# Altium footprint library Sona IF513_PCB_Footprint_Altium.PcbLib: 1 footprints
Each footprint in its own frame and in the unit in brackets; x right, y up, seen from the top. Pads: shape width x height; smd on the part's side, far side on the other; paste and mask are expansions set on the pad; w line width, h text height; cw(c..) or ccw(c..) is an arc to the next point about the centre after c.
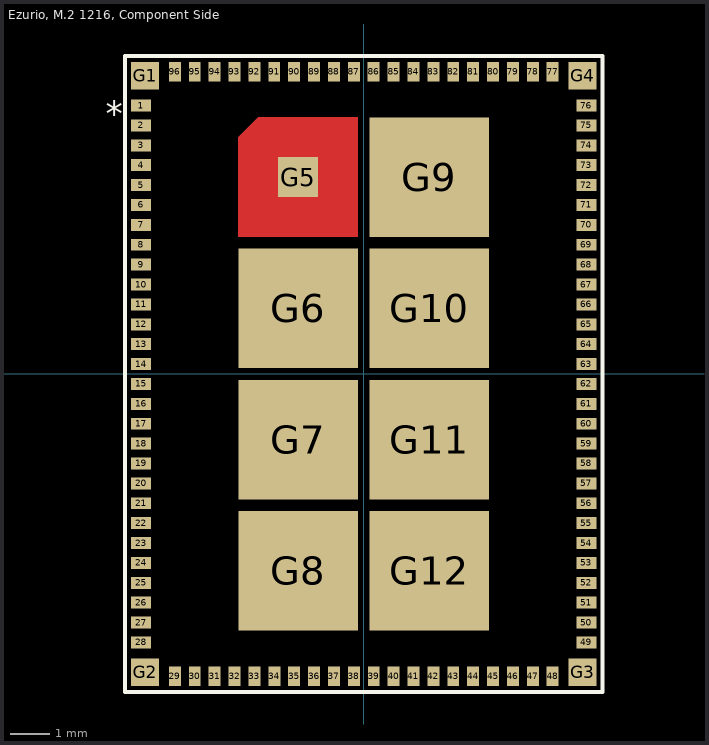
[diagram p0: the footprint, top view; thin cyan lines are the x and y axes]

## Ezurio, M.2 1216, Component Side [mm] "Ezurio, M2.1216, Component Side"
height 1.81
pads (108):
  rect 0.5x0.3 smd mask+0.051: 1(-5.6,6.75) 2(-5.6,6.25) 3(-5.6,5.75) 4(-5.6,5.25) 5(-5.6,4.75) 6(-5.6,4.25) 7(-5.6,3.75) 8(-5.6,3.25) 9(-5.6,2.75) 10(-5.6,2.25) 11(-5.6,1.75) 12(-5.6,1.25) 13(-5.6,0.75) 14(-5.6,0.25) 15(-5.6,-0.25) 16(-5.6,-0.75) 17(-5.6,-1.25) 18(-5.6,-1.75) 19(-5.6,-2.25) 20(-5.6,-2.75) 21(-5.6,-3.25) 22(-5.6,-3.75) 23(-5.6,-4.25) 24(-5.6,-4.75) 25(-5.6,-5.25) 26(-5.6,-5.75) 27(-5.6,-6.25) 28(-5.6,-6.75) 49(5.6,-6.75) 50(5.6,-6.25) 51(5.6,-5.75) 52(5.6,-5.25) 53(5.6,-4.75) 54(5.6,-4.25) 55(5.6,-3.75) 56(5.6,-3.25) 57(5.6,-2.75) 58(5.6,-2.25) 59(5.6,-1.75) 60(5.6,-1.25) 61(5.6,-0.75) 62(5.6,-0.25) 63(5.6,0.25) 64(5.6,0.75) 65(5.6,1.25) 66(5.6,1.75) 67(5.6,2.25) 68(5.6,2.75) 69(5.6,3.25) 70(5.6,3.75) 71(5.6,4.25) 72(5.6,4.75) 73(5.6,5.25) 74(5.6,5.75) 75(5.6,6.25) 76(5.6,6.75)
  rect 0.3x0.5 smd mask+0.051: 29(-4.749,-7.6) 30(-4.249,-7.6) 31(-3.75,-7.6) 32(-3.249,-7.6) 33(-2.75,-7.6) 34(-2.249,-7.6) 35(-1.749,-7.6) 36(-1.25,-7.6) 37(-0.749,-7.6) 38(-0.25,-7.6) 39(0.251,-7.6) 40(0.751,-7.6) 41(1.25,-7.6) 42(1.751,-7.6) 43(2.25,-7.6) 44(2.751,-7.6) 45(3.251,-7.6) 46(3.75,-7.6) 47(4.251,-7.6) 48(4.75,-7.6) 77(4.75,7.6) 78(4.25,7.6) 79(3.75,7.6) 80(3.25,7.6) 81(2.75,7.6) 82(2.25,7.6) 83(1.75,7.6) 84(1.25,7.6) 85(0.75,7.6) 86(0.25,7.6) 87(-0.25,7.6) 88(-0.75,7.6) 89(-1.25,7.6) 90(-1.75,7.6) 91(-2.25,7.6) 92(-2.75,7.6) 93(-3.25,7.6) 94(-3.75,7.6) 95(-4.25,7.6) 96(-4.75,7.6)
  rect 0.7x0.7 smd mask+0.051: G1(-5.5,7.5) G2(-5.5,-7.5) G3(5.5,-7.5) G4(5.5,7.5)
  rect 1x1 smd mask+0.051: G5(-1.65,4.95)
  rect 3x3 smd mask+0.051: G6(-1.65,1.65) G7(-1.65,-1.65) G8(-1.65,-4.95) G9(1.65,4.95) G10(1.65,1.65) G11(1.65,-1.65) G12(1.65,-4.95)
Top Layer:
  region: -2.65,6.45 -0.15,6.45 -0.15,3.45 -3.15,3.45 -3.15,5.95
Top Overlay:
  lines w0.102: -6,-8 6,-8 6,8 -6,8 -6,-8
  text "*" at -6.49,6.246 h0.64
Top Paste:
  region: -2.65,6.45 -0.15,6.45 -0.15,3.45 -3.15,3.45 -3.15,5.95
Top Solder:
  region: -2.669,6.5 -0.1,6.5 -0.1,3.4 -3.204,3.4 -3.204,5.965
Mechanical 13:
  lines w0.025: -6,4.2 -6,-8 ; 6,4.2 6,-8 ; -6,-8 -6,8 6,8 6,-8 ; -6,-8 6,-8 ; -6,-8 6,-8
  text "*" at -5.725,6.304 h0.64
  text ".Designator" at -6.66,8.617 h1.14
3D body: height 0.01, standoff 0, extent -3.15,3.45 -0.15,6.45
3D body: height 0.01, standoff 0, extent -5.85,-7.85 -5.15,-7.15
3D body: height 0.01, standoff 0, extent 0.15,3.45 3.15,6.45
3D body: height 0.01, standoff 0, extent 0.15,0.15 3.15,3.15
3D body: height 0.01, standoff 0, extent -3.15,0.15 -0.15,3.15
3D body: height 0.01, standoff 0, extent -3.15,-3.15 -0.15,-0.15
3D body: height 0.01, standoff 0, extent 0.15,-3.15 3.15,-0.15
3D body: height 0.01, standoff 0, extent 0.15,-6.45 3.15,-3.45
3D body: height 0.01, standoff 0, extent -3.15,-6.45 -0.15,-3.45
3D body: height 0.01, standoff 0, extent -5.85,-5.9 -5.35,-5.6
3D body: height 0.01, standoff 0, extent -5.85,-6.4 -5.35,-6.1
3D body: height 0.01, standoff 0, extent -5.85,-6.9 -5.35,-6.6
3D body: height 0.01, standoff 0, extent -5.85,-5.4 -5.35,-5.1
3D body: height 0.01, standoff 0, extent 5.15,-7.85 5.85,-7.15
3D body: height 0.01, standoff 0, extent 5.35,-6.9 5.85,-6.6
3D body: height 0.01, standoff 0, extent 5.35,-6.4 5.85,-6.1
3D body: height 0.01, standoff 0, extent 5.35,-5.9 5.85,-5.6
3D body: height 0.01, standoff 0, extent 5.35,-5.4 5.85,-5.1
3D body: height 0.01, standoff 0, extent 5.35,-4.9 5.85,-4.6
3D body: height 0.01, standoff 0, extent 5.35,-4.4 5.85,-4.1
3D body: height 0.01, standoff 0, extent 5.35,-3.9 5.85,-3.6
3D body: height 0.01, standoff 0, extent 5.35,-3.4 5.85,-3.1
3D body: height 0.01, standoff 0, extent 5.35,-2.9 5.85,-2.6
3D body: height 0.01, standoff 0, extent 5.35,-2.4 5.85,-2.1
3D body: height 0.01, standoff 0, extent 5.35,-1.9 5.85,-1.6
3D body: height 0.01, standoff 0, extent 5.35,-1.4 5.85,-1.1
3D body: height 0.01, standoff 0, extent 5.35,-0.9 5.85,-0.6
3D body: height 0.01, standoff 0, extent 5.35,-0.4 5.85,-0.1
3D body: height 0.01, standoff 0, extent 5.35,0.1 5.85,0.4
3D body: height 0.01, standoff 0, extent 5.35,0.6 5.85,0.9
3D body: height 0.01, standoff 0, extent 5.35,1.1 5.85,1.4
3D body: height 0.01, standoff 0, extent 5.35,1.6 5.85,1.9
3D body: height 0.01, standoff 0, extent 5.35,2.1 5.85,2.4
3D body: height 0.01, standoff 0, extent 5.35,2.6 5.85,2.9
3D body: height 0.01, standoff 0, extent 5.35,3.1 5.85,3.4
3D body: height 0.01, standoff 0, extent 5.35,3.6 5.85,3.9
3D body: height 0.01, standoff 0, extent 5.35,4.1 5.85,4.4
3D body: height 0.01, standoff 0, extent 5.35,4.6 5.85,4.9
3D body: height 0.01, standoff 0, extent 5.35,5.1 5.85,5.4
3D body: height 0.01, standoff 0, extent 5.35,5.6 5.85,5.9
3D body: height 0.01, standoff 0, extent 5.35,6.1 5.85,6.4
3D body: height 0.01, standoff 0, extent 5.35,6.6 5.85,6.9
3D body: height 0.01, standoff 0, extent 4.6,7.35 4.9,7.85
3D body: height 0.01, standoff 0, extent 4.1,7.35 4.4,7.85
3D body: height 0.01, standoff 0, extent 3.6,7.35 3.9,7.85
3D body: height 0.01, standoff 0, extent 3.1,7.35 3.4,7.85
3D body: height 0.01, standoff 0, extent 2.6,7.35 2.9,7.85
3D body: height 0.01, standoff 0, extent 2.1,7.35 2.4,7.85
3D body: height 0.01, standoff 0, extent 1.6,7.35 1.9,7.85
3D body: height 0.01, standoff 0, extent 1.1,7.35 1.4,7.85
3D body: height 0.01, standoff 0, extent 0.6,7.35 0.9,7.85
3D body: height 0.01, standoff 0, extent 0.1,7.35 0.4,7.85
3D body: height 0.01, standoff 0, extent -0.4,7.35 -0.1,7.85
3D body: height 0.01, standoff 0, extent -0.9,7.35 -0.6,7.85
3D body: height 0.01, standoff 0, extent -1.4,7.35 -1.1,7.85
3D body: height 0.01, standoff 0, extent -1.9,7.35 -1.6,7.85
3D body: height 0.01, standoff 0, extent -2.4,7.35 -2.1,7.85
3D body: height 0.01, standoff 0, extent -2.9,7.35 -2.6,7.85
3D body: height 0.01, standoff 0, extent -3.4,7.35 -3.1,7.85
3D body: height 0.01, standoff 0, extent -3.9,7.35 -3.6,7.85
3D body: height 0.01, standoff 0, extent -4.4,7.35 -4.1,7.85
3D body: height 0.01, standoff 0, extent -4.9,7.35 -4.6,7.85
3D body: height 0.01, standoff 0, extent -5.85,6.6 -5.35,6.9
3D body: height 0.01, standoff 0, extent -5.85,6.1 -5.35,6.4
3D body: height 0.01, standoff 0, extent -5.85,5.6 -5.35,5.9
3D body: height 0.01, standoff 0, extent -5.85,5.1 -5.35,5.4
3D body: height 0.01, standoff 0, extent -5.85,4.6 -5.35,4.9
3D body: height 0.01, standoff 0, extent -5.85,4.1 -5.35,4.4
3D body: height 0.01, standoff 0, extent -5.85,3.6 -5.35,3.9
3D body: height 0.01, standoff 0, extent -5.85,3.1 -5.35,3.4
3D body: height 0.01, standoff 0, extent -5.85,2.6 -5.35,2.9
3D body: height 0.01, standoff 0, extent -5.85,2.1 -5.35,2.4
3D body: height 0.01, standoff 0, extent -5.85,1.6 -5.35,1.9
3D body: height 0.01, standoff 0, extent -5.85,1.1 -5.35,1.4
3D body: height 0.01, standoff 0, extent -5.85,0.6 -5.35,0.9
3D body: height 0.01, standoff 0, extent -5.85,0.1 -5.35,0.4
3D body: height 0.01, standoff 0, extent -5.85,-0.4 -5.35,-0.1
3D body: height 0.01, standoff 0, extent -5.85,-0.9 -5.35,-0.6
3D body: height 0.01, standoff 0, extent -5.85,-1.4 -5.35,-1.1
3D body: height 0.01, standoff 0, extent -5.85,-1.9 -5.35,-1.6
3D body: height 0.01, standoff 0, extent -5.85,-2.4 -5.35,-2.1
3D body: height 0.01, standoff 0, extent -5.85,-2.9 -5.35,-2.6
3D body: height 0.01, standoff 0, extent -5.85,-3.4 -5.35,-3.1
3D body: height 0.01, standoff 0, extent -5.85,-3.9 -5.35,-3.6
3D body: height 0.01, standoff 0, extent -5.85,-4.4 -5.35,-4.1
3D body: height 0.01, standoff 0, extent -5.85,-4.9 -5.35,-4.6
3D body: height 0.01, standoff 0, extent -4.9,-7.85 -4.6,-7.35
3D body: height 0.01, standoff 0, extent -4.4,-7.85 -4.1,-7.35
3D body: height 0.01, standoff 0, extent -3.9,-7.85 -3.6,-7.35
3D body: height 0.01, standoff 0, extent -3.4,-7.85 -3.1,-7.35
3D body: height 0.01, standoff 0, extent -2.9,-7.85 -2.6,-7.35
3D body: height 0.01, standoff 0, extent -2.4,-7.85 -2.1,-7.35
3D body: height 0.01, standoff 0, extent -1.9,-7.85 -1.6,-7.35
3D body: height 0.01, standoff 0, extent -1.4,-7.85 -1.1,-7.35
3D body: height 0.01, standoff 0, extent -0.9,-7.85 -0.6,-7.35
3D body: height 0.01, standoff 0, extent -0.4,-7.85 -0.1,-7.35
3D body: height 0.01, standoff 0, extent 0.1,-7.85 0.4,-7.35
3D body: height 0.01, standoff 0, extent 0.6,-7.85 0.9,-7.35
3D body: height 0.01, standoff 0, extent 1.1,-7.85 1.4,-7.35
3D body: height 0.01, standoff 0, extent 1.6,-7.85 1.9,-7.35
3D body: height 0.01, standoff 0, extent 2.1,-7.85 2.4,-7.35
3D body: height 0.01, standoff 0, extent 2.6,-7.85 2.9,-7.35
3D body: height 0.01, standoff 0, extent 3.1,-7.85 3.4,-7.35
3D body: height 0.01, standoff 0, extent 3.6,-7.85 3.9,-7.35
3D body: height 0.01, standoff 0, extent 4.1,-7.85 4.4,-7.35
3D body: height 0.01, standoff 0, extent 4.6,-7.85 4.9,-7.35
3D body: height 0.01, standoff 0, extent -5.85,7.15 -5.15,7.85
3D body: height 0.01, standoff 0, extent 5.15,7.15 5.85,7.85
